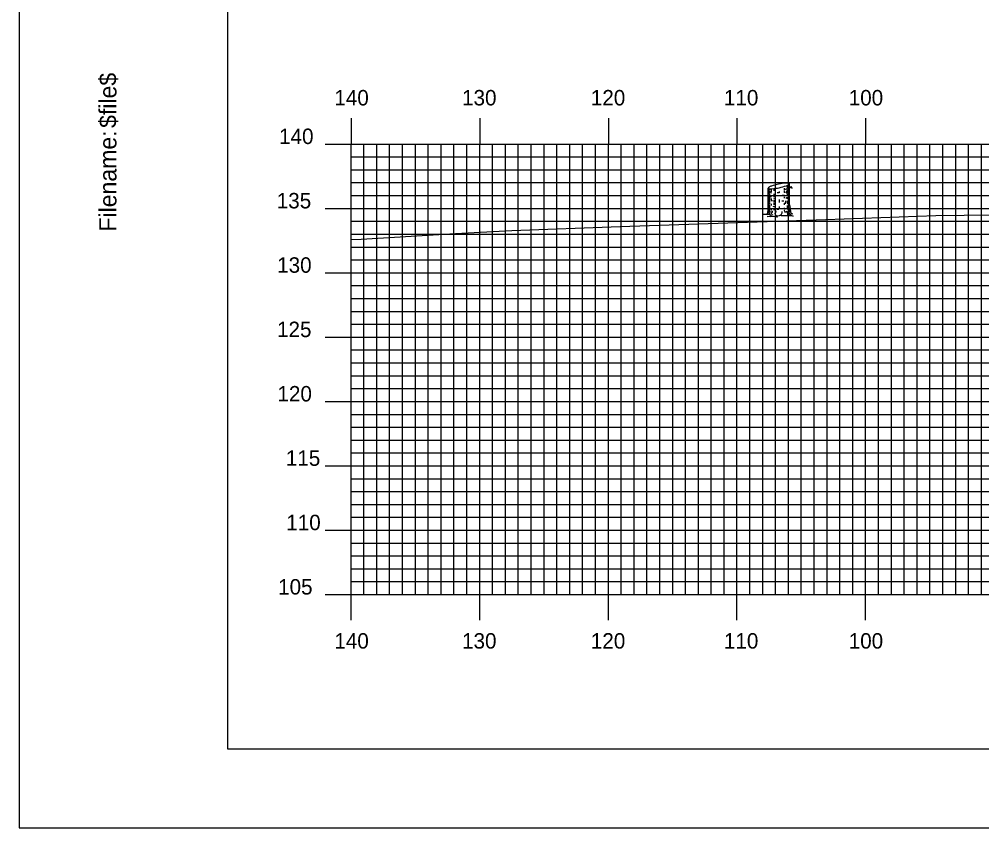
# Model space of a CAD drawing. Extents: x 1768087 to 1768430, y 442591 to 442811.
# Drawn here: x 1768087.2 to 1768162, y 442590.5 to 442653.4 of the extents above; entities that cross this region are included whole.
import ezdxf

# ---------------------------------------------------------------- set-up
doc = ezdxf.new("R2010")
doc.units = 0
for name, color, linetype in [('BORDER', 7, 'Continuous'), ('H_V ANNOTATION', 7, 'Continuous'), ('M_Trees_Conifer_Pay', 7, 'Continuous'), ('MAJOR', 7, 'Continuous'), ('MINOR', 7, 'Continuous'), ('PLOT BOUNDARY', 7, 'Continuous'), ('S_Roadway_Centerline', 7, 'Continuous')]:
    doc.layers.add(name, color=color, linetype=linetype)

msp = doc.modelspace()

# ---------------------------------------------------------------- linework, layer by layer
at = {"layer": 'BORDER'}
msp.add_lwpolyline([(1768103.363, 442596.665), (1768423.363, 442596.665), (1768423.363, 442806.665), (1768103.363, 442806.665)], close=True, dxfattribs=at)
at = {"layer": 'M_Trees_Conifer_Pay'}
for p, q in [((1768145.387, 442638.521), (1768145.387, 442640.243)), ((1768145.434, 442640.205), (1768145.434, 442639.734)), ((1768145.493, 442640.194), (1768145.493, 442640.097)), ((1768145.493, 442640.022), (1768145.493, 442639.818)), ((1768145.618, 442640.186), (1768145.618, 442639.954)), ((1768145.838, 442640.207), (1768145.838, 442640.039)), ((1768146.634, 442640.249), (1768146.634, 442640.049)), ((1768146.862, 442640.445), (1768146.862, 442640.222)), ((1768146.862, 442640.133), (1768146.862, 442640.086)), ((1768146.98, 442640.506), (1768146.98, 442640.343)), ((1768146.98, 442640.276), (1768146.98, 442640.148)), ((1768147.051, 442638.931), (1768147.051, 442640.578)), ((1768145.434, 442639.67), (1768145.434, 442639.362)), ((1768145.434, 442639.314), (1768145.434, 442638.822)), ((1768145.493, 442639.761), (1768145.493, 442639.561)), ((1768145.493, 442639.514), (1768145.493, 442639.178)), ((1768145.618, 442639.913), (1768145.618, 442639.839)), ((1768145.618, 442639.436), (1768145.618, 442639.297)), ((1768145.838, 442639.802), (1768145.838, 442639.565)), ((1768145.838, 442639.32), (1768145.838, 442639.168)), ((1768146.243, 442639.975), (1768146.243, 442639.88)), ((1768146.243, 442639.362), (1768146.243, 442639.287)), ((1768146.243, 442639.263), (1768146.243, 442639.114)), ((1768146.634, 442639.992), (1768146.634, 442639.903)), ((1768146.634, 442639.555), (1768146.634, 442639.45)), ((1768146.862, 442639.751), (1768146.862, 442639.619)), ((1768146.862, 442639.508), (1768146.862, 442639.398)), ((1768146.862, 442639.263), (1768146.862, 442639.121)), ((1768146.919, 442639.95), (1768146.868, 442639.89)), ((1768146.98, 442639.961), (1768146.98, 442639.625)), ((1768146.98, 442639.588), (1768146.98, 442639.425)), ((1768146.98, 442639.378), (1768146.98, 442639.161)), ((1768145.434, 442638.768), (1768145.434, 442638.521)), ((1768145.493, 442639.125), (1768145.493, 442638.989)), ((1768145.493, 442638.89), (1768145.493, 442638.511)), ((1768145.618, 442639.026), (1768145.618, 442638.884)), ((1768145.618, 442638.622), (1768145.618, 442638.528)), ((1768145.838, 442639.125), (1768145.838, 442638.951)), ((1768145.838, 442638.674), (1768145.838, 442638.521)), ((1768146.243, 442638.822), (1768146.243, 442638.669)), ((1768146.634, 442639.083), (1768146.634, 442638.937)), ((1768146.634, 442638.705), (1768146.634, 442638.616)), ((1768146.862, 442638.894), (1768146.862, 442638.721)), ((1768146.98, 442639.131), (1768146.98, 442639.056)), ((1768146.98, 442639.016), (1768146.98, 442638.843)), ((1768145.618, 442638.128), (1768145.781, 442638.192)), ((1768146.055, 442638.064), (1768145.929, 442638.128))]:
    msp.add_line(p, q, dxfattribs=at)
for points in [[(1768146.835, 442640.039), (1768146.804, 442639.954), (1768146.8, 442639.887), (1768146.831, 442639.823)], [(1768146.868, 442640.076), (1768146.905, 442640.002), (1768146.952, 442640.059), (1768147.01, 442640.127), (1768147.102, 442640.321), (1768147.167, 442640.368), (1768147.197, 442640.375)], [(1768146.883, 442639.823), (1768146.919, 442639.95), (1768146.983, 442640.066), (1768147.014, 442640.133), (1768147.083, 442640.28)], [(1768147.097, 442640.309), (1768147.173, 442640.317), (1768147.245, 442640.218)], [(1768145.566, 442639.549), (1768145.56, 442639.644), (1768145.604, 442639.621), (1768145.604, 442639.526)], [(1768147.051, 442638.931), (1768147.102, 442638.669), (1768147.119, 442638.396), (1768147.176, 442638.27), (1768147.312, 442638.24), (1768147.082, 442638.202), (1768147.082, 442638.202), (1768147.088, 442638.155), (1768147.335, 442638.06), (1768147.061, 442638.077), (1768146.705, 442638.097), (1768146.384, 442638.087), (1768146.39, 442638.169), (1768146.242, 442638.087), (1768146.055, 442638.064), (1768146.079, 442637.996), (1768145.812, 442638.039), (1768145.591, 442638.013), (1768145.299, 442638.03), (1768145.587, 442638.087), (1768145.618, 442638.128), (1768145.455, 442638.186), (1768145.218, 442638.196), (1768144.978, 442638.196), (1768145.32, 442638.254), (1768145.361, 442638.334), (1768145.387, 442638.521)], [(1768146.641, 442638.538), (1768146.652, 442638.412), (1768146.726, 442638.369)], [(1768146.705, 442639.15), (1768146.718, 442639.073), (1768146.765, 442639.083), (1768146.753, 442639.25)], [(1768146.878, 442638.643), (1768146.952, 442638.538), (1768146.957, 442638.365), (1768147.082, 442638.202)], [(1768146.977, 442638.789), (1768146.983, 442638.643), (1768147.03, 442638.575), (1768147.041, 442638.375)], [(1768145.435, 442638.474), (1768145.414, 442638.396), (1768145.394, 442638.301)], [(1768145.513, 442638.453), (1768145.519, 442638.338), (1768145.466, 442638.249), (1768145.455, 442638.186)], [(1768145.676, 442638.48), (1768145.676, 442638.348), (1768145.587, 442638.249)], [(1768145.902, 442638.24), (1768145.97, 442638.334), (1768145.997, 442638.474)], [(1768146.39, 442638.169), (1768146.465, 442638.311), (1768146.474, 442638.412)], [(1768146.919, 442638.149), (1768146.905, 442638.287), (1768146.831, 442638.416)]]:
    msp.add_lwpolyline(points, dxfattribs=at)
for centre, radius, start, end in [((1768145.419, 442640.065), 0.0334, 163.94846, 180), ((1768145.419, 442640.065), 0.0334, 180, 196.05154), ((1768145.414, 442640.243), 0.0264, 169.2194, 180.03145), ((1768145.41, 442640.243), 0.0226, 180.03145, 191.7194), ((1768145.43, 442640.068), 0.0441, 196.05154, 210), ((1768145.419, 442640.242), 0.0314, 156.51582, 169.2194), ((1768145.41, 442640.243), 0.0226, 191.7194, 203.40735), ((1768145.413, 442640.244), 0.0264, 203.40735, 214.2194), ((1768145.438, 442640.233), 0.0527, 146.7194, 156.51582), ((1768145.417, 442640.247), 0.0314, 214.2194, 226.92298), ((1768145.445, 442640.077), 0.0624, 210, 228.74941), ((1768145.462, 442640.217), 0.0817, 132.38868, 146.7194), ((1768145.432, 442640.262), 0.0527, 226.92298, 236.7194), ((1768145.448, 442640.287), 0.0817, 236.7194, 251.05013), ((1768145.518, 442640.159), 0.172, 228.74941, 240), ((1768145.576, 442640.092), 0.251, 124.2194, 132.38868), ((1768145.503, 442640.446), 0.251, 251.05013, 259.2194), ((1768145.717, 442640.504), 0.571, 240, 240.33672), ((1768145.886, 442639.637), 0.802, 108.05939, 124.2194), ((1768145.606, 442640.988), 0.802, 259.2194, 275.37941), ((1768147.243, 442635.475), 5.179, 101.7194, 108.05939), ((1768145.195, 442645.346), 5.179, 275.37941, 281.7194), ((1768146.219, 442644.255), 4.124, 264.6955, 266.73309), ((1768147.243, 442635.475), 5.179, 95.37941, 101.7194), ((1768145.195, 442645.346), 5.179, 281.7194, 288.05939), ((1768146.219, 442644.255), 4.124, 276.23804, 278.1032), ((1768146.833, 442639.833), 0.802, 79.2194, 95.37941), ((1768146.552, 442641.184), 0.802, 288.05939, 304.2194), ((1768146.72, 442640.737), 0.571, 278.1032, 284.36665), ((1768146.72, 442640.892), 0.571, 284.43166, 292.41325), ((1768146.72, 442640.737), 0.571, 297.0237, 300), ((1768146.936, 442640.375), 0.251, 71.05013, 79.2194), ((1768146.862, 442640.728), 0.251, 304.2194, 312.38868), ((1768146.919, 442640.547), 0.172, 300, 311.25059), ((1768146.919, 442640.392), 0.172, 300, 311.25059), ((1768146.991, 442640.534), 0.0817, 56.7194, 71.05013), ((1768146.976, 442640.604), 0.0817, 312.38868, 326.7194), ((1768146.992, 442640.464), 0.0624, 311.25059, 330), ((1768146.992, 442640.31), 0.0624, 311.25059, 330), ((1768147.006, 442640.558), 0.0527, 46.92298, 56.7194), ((1768147.021, 442640.574), 0.0314, 34.2194, 46.92298), ((1768147, 442640.588), 0.0527, 326.7194, 336.51582), ((1768147.008, 442640.455), 0.0441, 330, 343.94846), ((1768147.008, 442640.3), 0.0441, 330, 343.94846), ((1768147.025, 442640.577), 0.0264, 23.40735, 34.2194), ((1768147.029, 442640.578), 0.0226, 11.7194, 23.40735), ((1768147.02, 442640.579), 0.0314, 336.51582, 349.2194), ((1768147.018, 442640.452), 0.0334, 343.94846, 354.21506), ((1768147.018, 442640.297), 0.0334, 343.94846, 354.21506), ((1768147.029, 442640.578), 0.0226, 0.03145, 11.7194), ((1768147.025, 442640.578), 0.0264, 349.2194, 0.03145), ((1768145.419, 442639.618), 0.0334, 163.94846, 180), ((1768145.419, 442639.618), 0.0334, 180, 196.05154), ((1768145.419, 442639.408), 0.0334, 163.94846, 180), ((1768145.419, 442639.408), 0.0334, 180, 196.05154), ((1768145.43, 442639.621), 0.0441, 196.05154, 210), ((1768145.43, 442639.411), 0.0441, 196.05154, 210), ((1768145.445, 442639.63), 0.0624, 210, 228.74941), ((1768145.445, 442639.42), 0.0624, 210, 228.74941), ((1768145.518, 442639.712), 0.172, 228.74941, 240), ((1768145.518, 442639.502), 0.172, 228.74941, 240), ((1768145.717, 442640.058), 0.571, 240, 240.33672), ((1768145.717, 442639.848), 0.571, 240, 246.85973), ((1768145.718, 442640.293), 0.571, 240, 247.05866), ((1768145.717, 442640.504), 0.571, 246.85973, 257.98457), ((1768145.717, 442639.848), 0.571, 259.27072, 261.8968), ((1768146.218, 442643.365), 4.124, 261.8968, 263.14738), ((1768146.218, 442643.575), 4.124, 264.08098, 266.66759), ((1768146.218, 442644.022), 4.124, 268.07512, 270), ((1768146.218, 442644.022), 4.124, 270, 270.35814), ((1768146.219, 442643.811), 4.124, 273.70524, 275.95043), ((1768146.218, 442644.022), 4.124, 275.78493, 277.05584), ((1768146.218, 442643.575), 4.124, 277.61247, 278.1032), ((1768146.719, 442640.058), 0.571, 278.1032, 286.92962), ((1768146.72, 442640.293), 0.571, 284.44928, 297.04285), ((1768146.719, 442640.058), 0.571, 297.18959, 300), ((1768146.719, 442639.848), 0.571, 297.18959, 300), ((1768146.918, 442639.712), 0.172, 300, 311.25059), ((1768146.918, 442639.502), 0.172, 300, 311.25059), ((1768146.99, 442639.63), 0.0624, 311.25059, 330), ((1768146.99, 442639.42), 0.0624, 311.25059, 330), ((1768147.006, 442639.621), 0.0441, 330, 343.94846), ((1768147.006, 442639.411), 0.0441, 330, 343.94846), ((1768147.017, 442639.618), 0.0334, 343.94846, 354.21506), ((1768147.017, 442639.408), 0.0334, 343.94846, 354.21506), ((1768147.018, 442639.853), 0.0334, 343.94846, 354.21506), ((1768145.419, 442639.171), 0.0334, 163.94846, 180), ((1768145.419, 442639.171), 0.0334, 180, 196.05154), ((1768145.419, 442638.973), 0.0334, 163.94846, 180), ((1768145.419, 442638.778), 0.0334, 163.94846, 180), ((1768145.419, 442638.778), 0.0334, 180, 196.05154), ((1768145.419, 442638.557), 0.0334, 163.94846, 180), ((1768145.419, 442638.557), 0.0334, 180, 196.05154), ((1768145.43, 442639.174), 0.0441, 196.05154, 210), ((1768145.43, 442638.781), 0.0441, 196.05154, 210), ((1768145.43, 442638.56), 0.0441, 196.05154, 210), ((1768145.445, 442639.183), 0.0624, 210, 228.74941), ((1768145.445, 442638.79), 0.0624, 210, 228.74941), ((1768145.445, 442638.57), 0.0624, 210, 228.74941), ((1768145.518, 442639.266), 0.172, 228.74941, 240), ((1768145.518, 442638.872), 0.172, 228.74941, 240), ((1768145.518, 442638.652), 0.172, 228.74941, 240), ((1768145.717, 442639.611), 0.571, 240, 246.85973), ((1768145.706, 442639.419), 0.571, 241.23686, 248.02677), ((1768145.717, 442639.217), 0.571, 240, 246.85973), ((1768146.218, 442642.931), 4.124, 263.49906, 265.83975), ((1768146.218, 442643.128), 4.124, 264.71603, 266.31934), ((1768146.218, 442642.735), 4.124, 267.81166, 270), ((1768146.218, 442643.365), 4.124, 270, 270.35814), ((1768146.218, 442642.735), 4.124, 270, 270.13279), ((1768146.218, 442643.365), 4.124, 273.14934, 275.45691), ((1768146.218, 442642.735), 4.124, 275.78493, 276.78961), ((1768146.719, 442639.611), 0.571, 285.39827, 297.18959), ((1768146.719, 442639.217), 0.571, 288.50673, 297.27208), ((1768146.719, 442639.413), 0.571, 289.29072, 300), ((1768146.918, 442639.068), 0.172, 300, 311.25059), ((1768146.918, 442638.652), 0.172, 300, 311.25059), ((1768146.99, 442638.985), 0.0624, 311.25059, 330), ((1768146.99, 442638.57), 0.0624, 311.25059, 330), ((1768147.006, 442638.976), 0.0441, 330, 343.94846), ((1768147.006, 442638.56), 0.0441, 330, 343.94846), ((1768147.017, 442638.973), 0.0334, 343.94846, 354.21506), ((1768147.017, 442638.557), 0.0334, 343.94846, 354.21506), ((1768145.717, 442638.997), 0.571, 240, 244.53138), ((1768146.218, 442642.515), 4.124, 262.44379, 263.51202), ((1768146.218, 442642.515), 4.124, 277.36842, 278.1032), ((1768146.719, 442638.997), 0.571, 278.1032, 281.63703)]:
    msp.add_arc(centre, radius, start, end, dxfattribs=at)
at = {"layer": 'MAJOR'}
for p, q in [((1768112.963, 442645.669), (1768112.963, 442643.665)), ((1768122.963, 442645.669), (1768122.963, 442643.665)), ((1768132.963, 442645.669), (1768132.963, 442643.665)), ((1768142.963, 442645.669), (1768142.963, 442643.665)), ((1768152.963, 442645.669), (1768152.963, 442643.665)), ((1768110.959, 442643.665), (1768112.963, 442643.665)), ((1768112.963, 442643.665), (1768392.963, 442643.665)), ((1768112.963, 442608.665), (1768112.963, 442643.665)), ((1768112.963, 442608.665), (1768112.963, 442643.665)), ((1768112.963, 442643.665), (1768392.963, 442643.665)), ((1768122.963, 442608.665), (1768122.963, 442643.665)), ((1768132.963, 442608.665), (1768132.963, 442643.665)), ((1768142.963, 442608.665), (1768142.963, 442643.665)), ((1768152.963, 442608.665), (1768152.963, 442643.665)), ((1768110.959, 442638.665), (1768112.963, 442638.665)), ((1768112.963, 442638.665), (1768392.963, 442638.665)), ((1768110.959, 442633.665), (1768112.963, 442633.665)), ((1768112.963, 442633.665), (1768392.963, 442633.665)), ((1768110.959, 442628.665), (1768112.963, 442628.665)), ((1768112.963, 442628.665), (1768392.963, 442628.665)), ((1768110.959, 442623.665), (1768112.963, 442623.665)), ((1768112.963, 442623.665), (1768392.963, 442623.665)), ((1768110.959, 442618.665), (1768112.963, 442618.665)), ((1768112.963, 442618.665), (1768392.963, 442618.665)), ((1768110.959, 442613.665), (1768112.963, 442613.665)), ((1768112.963, 442613.665), (1768392.963, 442613.665)), ((1768110.959, 442608.665), (1768112.963, 442608.665)), ((1768112.963, 442608.665), (1768392.963, 442608.665)), ((1768112.963, 442608.665), (1768392.963, 442608.665)), ((1768112.963, 442606.661), (1768112.963, 442608.665)), ((1768122.963, 442606.661), (1768122.963, 442608.665)), ((1768132.963, 442606.661), (1768132.963, 442608.665)), ((1768142.963, 442606.661), (1768142.963, 442608.665)), ((1768152.963, 442606.661), (1768152.963, 442608.665))]:
    msp.add_line(p, q, dxfattribs=at)
at = {"layer": 'MINOR'}
for p, q in [((1768113.963, 442608.665), (1768113.963, 442643.665)), ((1768114.963, 442608.665), (1768114.963, 442643.665)), ((1768115.963, 442608.665), (1768115.963, 442643.665)), ((1768116.963, 442608.665), (1768116.963, 442643.665)), ((1768117.963, 442608.665), (1768117.963, 442643.665)), ((1768118.963, 442608.665), (1768118.963, 442643.665)), ((1768119.963, 442608.665), (1768119.963, 442643.665)), ((1768120.963, 442608.665), (1768120.963, 442643.665)), ((1768121.963, 442608.665), (1768121.963, 442643.665)), ((1768123.963, 442608.665), (1768123.963, 442643.665)), ((1768124.963, 442608.665), (1768124.963, 442643.665)), ((1768125.963, 442608.665), (1768125.963, 442643.665)), ((1768126.963, 442608.665), (1768126.963, 442643.665)), ((1768127.963, 442608.665), (1768127.963, 442643.665)), ((1768128.963, 442608.665), (1768128.963, 442643.665)), ((1768129.963, 442608.665), (1768129.963, 442643.665)), ((1768130.963, 442608.665), (1768130.963, 442643.665)), ((1768131.963, 442608.665), (1768131.963, 442643.665)), ((1768133.963, 442608.665), (1768133.963, 442643.665)), ((1768134.963, 442608.665), (1768134.963, 442643.665)), ((1768135.963, 442608.665), (1768135.963, 442643.665)), ((1768136.963, 442608.665), (1768136.963, 442643.665)), ((1768137.963, 442608.665), (1768137.963, 442643.665)), ((1768138.963, 442608.665), (1768138.963, 442643.665)), ((1768139.963, 442608.665), (1768139.963, 442643.665)), ((1768140.963, 442608.665), (1768140.963, 442643.665)), ((1768141.963, 442608.665), (1768141.963, 442643.665)), ((1768143.963, 442608.665), (1768143.963, 442643.665)), ((1768144.963, 442608.665), (1768144.963, 442643.665)), ((1768145.963, 442608.665), (1768145.963, 442643.665)), ((1768146.963, 442608.665), (1768146.963, 442643.665)), ((1768147.963, 442608.665), (1768147.963, 442643.665)), ((1768148.963, 442608.665), (1768148.963, 442643.665)), ((1768149.963, 442608.665), (1768149.963, 442643.665)), ((1768150.963, 442608.665), (1768150.963, 442643.665)), ((1768151.963, 442608.665), (1768151.963, 442643.665)), ((1768153.963, 442608.665), (1768153.963, 442643.665)), ((1768154.963, 442608.665), (1768154.963, 442643.665)), ((1768155.963, 442608.665), (1768155.963, 442643.665)), ((1768156.963, 442608.665), (1768156.963, 442643.665)), ((1768157.963, 442608.665), (1768157.963, 442643.665)), ((1768158.963, 442608.665), (1768158.963, 442643.665)), ((1768159.963, 442608.665), (1768159.963, 442643.665)), ((1768160.963, 442608.665), (1768160.963, 442643.665)), ((1768161.963, 442608.665), (1768161.963, 442643.665)), ((1768112.963, 442642.665), (1768392.963, 442642.665)), ((1768112.963, 442642.665), (1768114.967, 442642.665)), ((1768112.963, 442641.665), (1768392.963, 442641.665)), ((1768112.963, 442641.665), (1768114.967, 442641.665)), ((1768112.963, 442640.665), (1768392.963, 442640.665)), ((1768112.963, 442640.665), (1768114.967, 442640.665)), ((1768112.963, 442639.665), (1768392.963, 442639.665)), ((1768112.963, 442639.665), (1768114.967, 442639.665)), ((1768112.963, 442637.665), (1768392.963, 442637.665)), ((1768112.963, 442637.665), (1768114.967, 442637.665)), ((1768112.963, 442636.665), (1768392.963, 442636.665)), ((1768112.963, 442636.665), (1768114.967, 442636.665)), ((1768112.963, 442635.665), (1768392.963, 442635.665)), ((1768112.963, 442635.665), (1768114.967, 442635.665)), ((1768112.963, 442634.665), (1768392.963, 442634.665)), ((1768112.963, 442634.665), (1768114.967, 442634.665)), ((1768112.963, 442632.665), (1768392.963, 442632.665)), ((1768112.963, 442632.665), (1768114.967, 442632.665)), ((1768112.963, 442631.665), (1768392.963, 442631.665)), ((1768112.963, 442631.665), (1768114.967, 442631.665)), ((1768112.963, 442630.665), (1768392.963, 442630.665)), ((1768112.963, 442630.665), (1768114.967, 442630.665)), ((1768112.963, 442629.665), (1768392.963, 442629.665)), ((1768112.963, 442629.665), (1768114.967, 442629.665)), ((1768112.963, 442627.665), (1768392.963, 442627.665)), ((1768112.963, 442627.665), (1768114.967, 442627.665)), ((1768112.963, 442626.665), (1768392.963, 442626.665)), ((1768112.963, 442626.665), (1768114.967, 442626.665)), ((1768112.963, 442625.665), (1768392.963, 442625.665)), ((1768112.963, 442625.665), (1768114.967, 442625.665)), ((1768112.963, 442624.665), (1768392.963, 442624.665)), ((1768112.963, 442624.665), (1768114.967, 442624.665)), ((1768112.963, 442622.665), (1768392.963, 442622.665)), ((1768112.963, 442622.665), (1768114.967, 442622.665)), ((1768112.963, 442621.665), (1768392.963, 442621.665)), ((1768112.963, 442621.665), (1768114.967, 442621.665)), ((1768112.963, 442620.665), (1768392.963, 442620.665)), ((1768112.963, 442620.665), (1768114.967, 442620.665)), ((1768112.963, 442619.665), (1768392.963, 442619.665)), ((1768112.963, 442619.665), (1768114.967, 442619.665)), ((1768112.963, 442617.665), (1768392.963, 442617.665)), ((1768112.963, 442617.665), (1768114.967, 442617.665)), ((1768112.963, 442616.665), (1768392.963, 442616.665)), ((1768112.963, 442616.665), (1768114.967, 442616.665)), ((1768112.963, 442615.665), (1768392.963, 442615.665)), ((1768112.963, 442615.665), (1768114.967, 442615.665)), ((1768112.963, 442614.665), (1768392.963, 442614.665)), ((1768112.963, 442614.665), (1768114.967, 442614.665)), ((1768112.963, 442612.665), (1768392.963, 442612.665)), ((1768112.963, 442612.665), (1768114.967, 442612.665)), ((1768112.963, 442611.665), (1768392.963, 442611.665)), ((1768112.963, 442611.665), (1768114.967, 442611.665)), ((1768112.963, 442610.665), (1768392.963, 442610.665)), ((1768112.963, 442610.665), (1768114.967, 442610.665)), ((1768112.963, 442609.665), (1768392.963, 442609.665)), ((1768112.963, 442609.665), (1768114.967, 442609.665))]:
    msp.add_line(p, q, dxfattribs=at)
at = {"layer": 'PLOT BOUNDARY'}
msp.add_lwpolyline([(1768087.176, 442590.547), (1768427.176, 442590.547), (1768427.176, 442810.547), (1768087.176, 442810.547)], close=True, dxfattribs=at)
at = {"layer": 'S_Roadway_Centerline'}
msp.add_lwpolyline([(1768112.963, 442636.247), (1768113.754, 442636.262), (1768121.082, 442636.71), (1768125.458, 442636.936), (1768133.88, 442637.265), (1768149.87, 442637.812), (1768158.42, 442638.115), (1768165.043, 442638.182)], dxfattribs=at)

# ---------------------------------------------------------------- texts
at = {"layer": 'BORDER'}
for s, p in [('$file$', (1768094.732, 442644.916)), ('Filename:', (1768094.732, 442636.862))]:
    msp.add_text(s, height=1.3392, rotation=90, dxfattribs=at).set_placement(p)
at = {"layer": 'H_V ANNOTATION'}
for s, p in [('140', (1768111.667, 442646.665)), ('130', (1768121.593, 442646.665)), ('120', (1768131.603, 442646.665)), ('110', (1768141.946, 442646.665)), ('100', (1768151.646, 442646.665)), ('140', (1768107.372, 442643.665)), ('135', (1768107.19, 442638.665)), ('130', (1768107.222, 442633.665)), ('125', (1768107.212, 442628.665)), ('120', (1768107.244, 442623.665)), ('115', (1768107.897, 442618.665)), ('110', (1768107.929, 442613.665)), ('105', (1768107.297, 442608.665)), ('140', (1768111.667, 442604.465)), ('130', (1768121.593, 442604.465)), ('120', (1768131.603, 442604.465)), ('110', (1768141.946, 442604.465)), ('100', (1768151.646, 442604.465))]:
    msp.add_text(s, height=1.2, dxfattribs=at).set_placement(p)
at = {"layer": 'MAJOR'}
msp.add_text('-', height=0.012, dxfattribs=at).set_placement((1768112.954, 442608.665))

doc.saveas('drawing.dxf')
